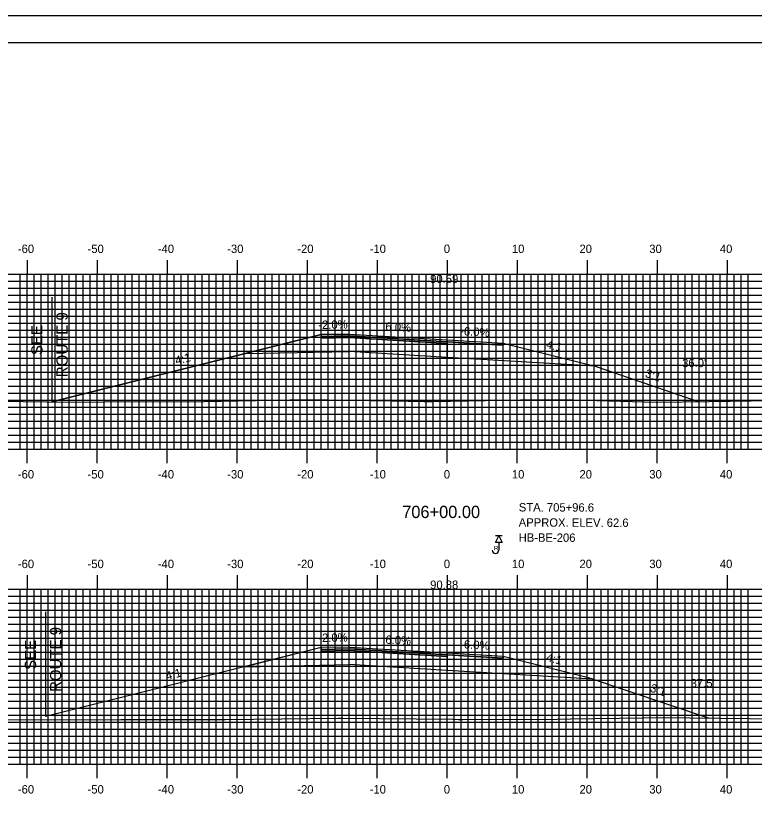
# Model space of a CAD drawing. Extents: x 853723 to 854066, y 364366 to 364586.
# Drawn here: x 853827.1 to 853932.6, y 364472.6 to 364585.7 of the extents above; entities that cross this region are included whole.
import ezdxf

# ---------------------------------------------------------------- set-up
doc = ezdxf.new("R2010")
doc.units = 0
for name, color, linetype in [('ANNOTATION', 7, 'Continuous'), ('BORDER', 7, 'Continuous'), ('BORING - REFUSAL', 7, 'Continuous'), ('D_Roadway_Centerline', 7, 'Continuous'), ('D_Roadway_Centerline_Text', 7, 'Continuous'), ('D_Roadway_Edge_Shoulder', 7, 'Continuous'), ('D_Roadway_Edge_TW', 7, 'Continuous'), ('D_Roadway_Pavement', 7, 'Continuous'), ('D_Roadway_SlopeLines', 7, 'Continuous'), ('D_Roadway_SubGrade', 7, 'Continuous'), ('D_Text_Standard', 7, 'Continuous'), ('H_V ANNOTATION', 7, 'Continuous'), ('MAJOR', 7, 'Continuous'), ('MINOR', 7, 'Continuous'), ('PLOT BOUNDARY', 7, 'Continuous'), ('S_Roadway_Centerline', 7, 'Continuous')]:
    doc.layers.add(name, color=color, linetype=linetype)

msp = doc.modelspace()

# ---------------------------------------------------------------- linework, layer by layer
at = {"layer": 'BORDER'}
msp.add_lwpolyline([(853739.12, 364371.79), (854059.12, 364371.79), (854059.12, 364581.79), (853739.12, 364581.79)], close=True, dxfattribs=at)
at = {"layer": 'BORING - REFUSAL'}
for p, q in [((853896.6, 364511.39), (853895.64, 364511.39)), ((853896.12, 364510.43), (853896.12, 364509.37))]:
    msp.add_line(p, q, dxfattribs=at)
msp.add_lwpolyline([(853896.12, 364511.39), (853896.6, 364510.43), (853895.64, 364510.43)], close=True, dxfattribs=at)
msp.add_arc((853895.63, 364509.37), 0.485, 180, 0, dxfattribs=at)
at = {"layer": 'D_Roadway_Centerline'}
msp.add_lwpolyline([(853832.23, 364530.52), (853859.85, 364537.42), (853870.72, 364540.14), (853874.72, 364540.22), (853888.72, 364539.38), (853896.72, 364538.9), (853908.72, 364535.9), (853909.88, 364535.61), (853924.73, 364530.56)], dxfattribs=at)
at = {"layer": 'D_Roadway_Edge_Shoulder'}
for points in [[(853874.72, 364540.22), (853870.72, 364540.14), (853870.72, 364539.89), (853874.72, 364539.97)], [(853888.72, 364539.38), (853896.72, 364538.9), (853896.72, 364538.65), (853888.72, 364539.13)], [(853874.72, 364495.51), (853870.72, 364495.43), (853870.72, 364495.18), (853874.72, 364495.26)], [(853888.72, 364494.67), (853896.72, 364494.19), (853896.72, 364493.94), (853888.72, 364494.42)]]:
    msp.add_lwpolyline(points, close=True, dxfattribs=at)
at = {"layer": 'D_Roadway_Edge_TW'}
for points in [[(853874.72, 364540.22), (853888.72, 364539.38), (853888.72, 364539.13), (853874.72, 364539.97)], [(853874.72, 364495.51), (853888.72, 364494.67), (853888.72, 364494.42), (853874.72, 364495.26)]]:
    msp.add_lwpolyline(points, close=True, dxfattribs=at)
at = {"layer": 'D_Roadway_Pavement'}
for points in [[(853874.72, 364539.97), (853870.72, 364539.89), (853870.72, 364539.64), (853874.72, 364539.72)], [(853874.72, 364539.97), (853888.72, 364539.13), (853888.72, 364538.88), (853874.72, 364539.72)], [(853874.72, 364495.26), (853870.72, 364495.18), (853870.72, 364494.93), (853874.72, 364495.01)], [(853874.72, 364495.26), (853888.72, 364494.42), (853888.72, 364494.17), (853874.72, 364495.01)]]:
    msp.add_lwpolyline(points, close=True, dxfattribs=at)
for points in [[(853888.72, 364539.13), (853888.72, 364538.88)], [(853888.72, 364539.13), (853888.72, 364538.88)], [(853888.72, 364494.42), (853888.72, 364494.17)], [(853888.72, 364494.42), (853888.72, 364494.17)]]:
    msp.add_lwpolyline(points, dxfattribs=at)
at = {"layer": 'D_Roadway_SlopeLines'}
for points in [[(853870.72, 364540.14), (853832.23, 364530.52)], [(853896.72, 364538.9), (853908.72, 364535.9), (853909.88, 364535.61), (853924.73, 364530.56)], [(853870.72, 364495.43), (853831.31, 364485.58)], [(853896.72, 364494.19), (853908.72, 364491.19), (853926.17, 364485.37)]]:
    msp.add_lwpolyline(points, dxfattribs=at)
at = {"layer": 'D_Roadway_SubGrade'}
for p, q in [((853832.23, 364545.48), (853832.23, 364530.52)), ((853831.31, 364500.53), (853831.31, 364485.58))]:
    msp.add_line(p, q, dxfattribs=at)
for points in [[(853874.72, 364539.72), (853870.72, 364539.64), (853870.72, 364539.89), (853870.72, 364540.14), (853859.85, 364537.42), (853874.72, 364537.72)], [(853874.72, 364539.72), (853888.72, 364538.88), (853888.72, 364536.88), (853874.72, 364537.72)], [(853888.72, 364538.88), (853888.72, 364539.13), (853896.72, 364538.65), (853896.72, 364538.9), (853909.88, 364535.61), (853888.72, 364536.88)], [(853874.72, 364495.01), (853870.72, 364494.93), (853870.72, 364495.18), (853870.72, 364495.43), (853859.85, 364492.71), (853874.72, 364493.01)], [(853874.72, 364495.01), (853888.72, 364494.17), (853888.72, 364492.17), (853874.72, 364493.01)], [(853888.72, 364494.17), (853888.72, 364494.42), (853896.72, 364493.94), (853896.72, 364494.19), (853908.72, 364491.19), (853909.52, 364490.92), (853888.72, 364492.17)]]:
    msp.add_lwpolyline(points, close=True, dxfattribs=at)
at = {"layer": 'MAJOR'}
for p, q in [((853828.72, 364550.79), (853828.72, 364548.79)), ((853838.72, 364550.79), (853838.72, 364548.79)), ((853848.72, 364550.79), (853848.72, 364548.79)), ((853858.72, 364550.79), (853858.72, 364548.79)), ((853868.72, 364550.79), (853868.72, 364548.79)), ((853878.72, 364550.79), (853878.72, 364548.79)), ((853888.72, 364550.79), (853888.72, 364548.79)), ((853898.72, 364550.79), (853898.72, 364548.79)), ((853908.72, 364550.79), (853908.72, 364548.79)), ((853918.72, 364550.79), (853918.72, 364548.79)), ((853928.72, 364550.79), (853928.72, 364548.79)), ((853748.72, 364548.79), (854028.72, 364548.79)), ((853748.72, 364548.79), (854028.72, 364548.79)), ((853828.72, 364523.79), (853828.72, 364548.79)), ((853838.72, 364523.79), (853838.72, 364548.79)), ((853848.72, 364523.79), (853848.72, 364548.79)), ((853858.72, 364523.79), (853858.72, 364548.79)), ((853868.72, 364523.79), (853868.72, 364548.79)), ((853878.72, 364523.79), (853878.72, 364548.79)), ((853888.72, 364523.79), (853888.72, 364548.79)), ((853898.72, 364523.79), (853898.72, 364548.79)), ((853908.72, 364523.79), (853908.72, 364548.79)), ((853918.72, 364523.79), (853918.72, 364548.79)), ((853928.72, 364523.79), (853928.72, 364548.79)), ((853748.72, 364543.79), (854028.72, 364543.79)), ((853748.72, 364538.79), (854028.72, 364538.79)), ((853748.72, 364533.79), (854028.72, 364533.79)), ((853748.72, 364528.79), (854028.72, 364528.79)), ((853748.72, 364523.79), (854028.72, 364523.79)), ((853748.72, 364523.79), (854028.72, 364523.79)), ((853828.72, 364521.78), (853828.72, 364523.79)), ((853838.72, 364521.78), (853838.72, 364523.79)), ((853848.72, 364521.78), (853848.72, 364523.79)), ((853858.72, 364521.78), (853858.72, 364523.79)), ((853868.72, 364521.78), (853868.72, 364523.79)), ((853878.72, 364521.78), (853878.72, 364523.79)), ((853888.72, 364521.78), (853888.72, 364523.79)), ((853898.72, 364521.78), (853898.72, 364523.79)), ((853908.72, 364521.78), (853908.72, 364523.79)), ((853918.72, 364521.78), (853918.72, 364523.79)), ((853928.72, 364521.78), (853928.72, 364523.79)), ((853828.72, 364505.79), (853828.72, 364503.79)), ((853838.72, 364505.79), (853838.72, 364503.79)), ((853848.72, 364505.79), (853848.72, 364503.79)), ((853858.72, 364505.79), (853858.72, 364503.79)), ((853868.72, 364505.79), (853868.72, 364503.79)), ((853878.72, 364505.79), (853878.72, 364503.79)), ((853888.72, 364505.79), (853888.72, 364503.79)), ((853898.72, 364505.79), (853898.72, 364503.79)), ((853908.72, 364505.79), (853908.72, 364503.79)), ((853918.72, 364505.79), (853918.72, 364503.79)), ((853928.72, 364505.79), (853928.72, 364503.79)), ((853748.72, 364503.79), (854028.72, 364503.79)), ((853748.72, 364503.79), (854028.72, 364503.79)), ((853828.72, 364478.79), (853828.72, 364503.79)), ((853838.72, 364478.79), (853838.72, 364503.79)), ((853848.72, 364478.79), (853848.72, 364503.79)), ((853858.72, 364478.79), (853858.72, 364503.79)), ((853868.72, 364478.79), (853868.72, 364503.79)), ((853878.72, 364478.79), (853878.72, 364503.79)), ((853888.72, 364478.79), (853888.72, 364503.79)), ((853898.72, 364478.79), (853898.72, 364503.79)), ((853908.72, 364478.79), (853908.72, 364503.79)), ((853918.72, 364478.79), (853918.72, 364503.79)), ((853928.72, 364478.79), (853928.72, 364503.79)), ((853748.72, 364498.79), (854028.72, 364498.79)), ((853748.72, 364493.79), (854028.72, 364493.79)), ((853748.72, 364488.79), (854028.72, 364488.79)), ((853748.72, 364483.79), (854028.72, 364483.79)), ((853748.72, 364478.79), (854028.72, 364478.79)), ((853748.72, 364478.79), (854028.72, 364478.79)), ((853828.72, 364476.78), (853828.72, 364478.79)), ((853838.72, 364476.78), (853838.72, 364478.79)), ((853848.72, 364476.78), (853848.72, 364478.79)), ((853858.72, 364476.78), (853858.72, 364478.79)), ((853868.72, 364476.78), (853868.72, 364478.79)), ((853878.72, 364476.78), (853878.72, 364478.79)), ((853888.72, 364476.78), (853888.72, 364478.79)), ((853898.72, 364476.78), (853898.72, 364478.79)), ((853908.72, 364476.78), (853908.72, 364478.79)), ((853918.72, 364476.78), (853918.72, 364478.79)), ((853928.72, 364476.78), (853928.72, 364478.79))]:
    msp.add_line(p, q, dxfattribs=at)
at = {"layer": 'MINOR'}
for p, q in [((853827.72, 364523.79), (853827.72, 364548.79)), ((853829.72, 364523.79), (853829.72, 364548.79)), ((853830.72, 364523.79), (853830.72, 364548.79)), ((853831.72, 364523.79), (853831.72, 364548.79)), ((853832.72, 364523.79), (853832.72, 364548.79)), ((853833.72, 364523.79), (853833.72, 364548.79)), ((853834.72, 364523.79), (853834.72, 364548.79)), ((853835.72, 364523.79), (853835.72, 364548.79)), ((853836.72, 364523.79), (853836.72, 364548.79)), ((853837.72, 364523.79), (853837.72, 364548.79)), ((853839.72, 364523.79), (853839.72, 364548.79)), ((853840.72, 364523.79), (853840.72, 364548.79)), ((853841.72, 364523.79), (853841.72, 364548.79)), ((853842.72, 364523.79), (853842.72, 364548.79)), ((853843.72, 364523.79), (853843.72, 364548.79)), ((853844.72, 364523.79), (853844.72, 364548.79)), ((853845.72, 364523.79), (853845.72, 364548.79)), ((853846.72, 364523.79), (853846.72, 364548.79)), ((853847.72, 364523.79), (853847.72, 364548.79)), ((853849.72, 364523.79), (853849.72, 364548.79)), ((853850.72, 364523.79), (853850.72, 364548.79)), ((853851.72, 364523.79), (853851.72, 364548.79)), ((853852.72, 364523.79), (853852.72, 364548.79)), ((853853.72, 364523.79), (853853.72, 364548.79)), ((853854.72, 364523.79), (853854.72, 364548.79)), ((853855.72, 364523.79), (853855.72, 364548.79)), ((853856.72, 364523.79), (853856.72, 364548.79)), ((853857.72, 364523.79), (853857.72, 364548.79)), ((853859.72, 364523.79), (853859.72, 364548.79)), ((853860.72, 364523.79), (853860.72, 364548.79)), ((853861.72, 364523.79), (853861.72, 364548.79)), ((853862.72, 364523.79), (853862.72, 364548.79)), ((853863.72, 364523.79), (853863.72, 364548.79)), ((853864.72, 364523.79), (853864.72, 364548.79)), ((853865.72, 364523.79), (853865.72, 364548.79)), ((853866.72, 364523.79), (853866.72, 364548.79)), ((853867.72, 364523.79), (853867.72, 364548.79)), ((853869.72, 364523.79), (853869.72, 364548.79)), ((853870.72, 364523.79), (853870.72, 364548.79)), ((853871.72, 364523.79), (853871.72, 364548.79)), ((853872.72, 364523.79), (853872.72, 364548.79)), ((853873.72, 364523.79), (853873.72, 364548.79)), ((853874.72, 364523.79), (853874.72, 364548.79)), ((853875.72, 364523.79), (853875.72, 364548.79)), ((853876.72, 364523.79), (853876.72, 364548.79)), ((853877.72, 364523.79), (853877.72, 364548.79)), ((853879.72, 364523.79), (853879.72, 364548.79)), ((853880.72, 364523.79), (853880.72, 364548.79)), ((853881.72, 364523.79), (853881.72, 364548.79)), ((853882.72, 364523.79), (853882.72, 364548.79)), ((853883.72, 364523.79), (853883.72, 364548.79)), ((853884.72, 364523.79), (853884.72, 364548.79)), ((853885.72, 364523.79), (853885.72, 364548.79)), ((853886.72, 364523.79), (853886.72, 364548.79)), ((853887.72, 364523.79), (853887.72, 364548.79)), ((853889.72, 364523.79), (853889.72, 364548.79)), ((853890.72, 364523.79), (853890.72, 364548.79)), ((853891.72, 364523.79), (853891.72, 364548.79)), ((853892.72, 364523.79), (853892.72, 364548.79)), ((853893.72, 364523.79), (853893.72, 364548.79)), ((853894.72, 364523.79), (853894.72, 364548.79)), ((853895.72, 364523.79), (853895.72, 364548.79)), ((853896.72, 364523.79), (853896.72, 364548.79)), ((853897.72, 364523.79), (853897.72, 364548.79)), ((853899.72, 364523.79), (853899.72, 364548.79)), ((853900.72, 364523.79), (853900.72, 364548.79)), ((853901.72, 364523.79), (853901.72, 364548.79)), ((853902.72, 364523.79), (853902.72, 364548.79)), ((853903.72, 364523.79), (853903.72, 364548.79)), ((853904.72, 364523.79), (853904.72, 364548.79)), ((853905.72, 364523.79), (853905.72, 364548.79)), ((853906.72, 364523.79), (853906.72, 364548.79)), ((853907.72, 364523.79), (853907.72, 364548.79)), ((853909.72, 364523.79), (853909.72, 364548.79)), ((853910.72, 364523.79), (853910.72, 364548.79)), ((853911.72, 364523.79), (853911.72, 364548.79)), ((853912.72, 364523.79), (853912.72, 364548.79)), ((853913.72, 364523.79), (853913.72, 364548.79)), ((853914.72, 364523.79), (853914.72, 364548.79)), ((853915.72, 364523.79), (853915.72, 364548.79)), ((853916.72, 364523.79), (853916.72, 364548.79)), ((853917.72, 364523.79), (853917.72, 364548.79)), ((853919.72, 364523.79), (853919.72, 364548.79)), ((853920.72, 364523.79), (853920.72, 364548.79)), ((853921.72, 364523.79), (853921.72, 364548.79)), ((853922.72, 364523.79), (853922.72, 364548.79)), ((853923.72, 364523.79), (853923.72, 364548.79)), ((853924.72, 364523.79), (853924.72, 364548.79)), ((853925.72, 364523.79), (853925.72, 364548.79)), ((853926.72, 364523.79), (853926.72, 364548.79)), ((853927.72, 364523.79), (853927.72, 364548.79)), ((853929.72, 364523.79), (853929.72, 364548.79)), ((853930.72, 364523.79), (853930.72, 364548.79)), ((853931.72, 364523.79), (853931.72, 364548.79)), ((853748.72, 364547.79), (854028.72, 364547.79)), ((853748.72, 364546.79), (854028.72, 364546.79)), ((853748.72, 364545.79), (854028.72, 364545.79)), ((853748.72, 364544.79), (854028.72, 364544.79)), ((853748.72, 364542.79), (854028.72, 364542.79)), ((853748.72, 364541.79), (854028.72, 364541.79)), ((853748.72, 364540.79), (854028.72, 364540.79)), ((853748.72, 364539.79), (854028.72, 364539.79)), ((853748.72, 364537.79), (854028.72, 364537.79)), ((853748.72, 364536.79), (854028.72, 364536.79)), ((853748.72, 364535.79), (854028.72, 364535.79)), ((853748.72, 364534.79), (854028.72, 364534.79)), ((853748.72, 364532.79), (854028.72, 364532.79)), ((853748.72, 364531.79), (854028.72, 364531.79)), ((853748.72, 364530.79), (854028.72, 364530.79)), ((853748.72, 364529.79), (854028.72, 364529.79)), ((853748.72, 364527.79), (854028.72, 364527.79)), ((853748.72, 364526.79), (854028.72, 364526.79)), ((853748.72, 364525.79), (854028.72, 364525.79)), ((853748.72, 364524.79), (854028.72, 364524.79)), ((853827.72, 364478.79), (853827.72, 364503.79)), ((853829.72, 364478.79), (853829.72, 364503.79)), ((853830.72, 364478.79), (853830.72, 364503.79)), ((853831.72, 364478.79), (853831.72, 364503.79)), ((853832.72, 364478.79), (853832.72, 364503.79)), ((853833.72, 364478.79), (853833.72, 364503.79)), ((853834.72, 364478.79), (853834.72, 364503.79)), ((853835.72, 364478.79), (853835.72, 364503.79)), ((853836.72, 364478.79), (853836.72, 364503.79)), ((853837.72, 364478.79), (853837.72, 364503.79)), ((853839.72, 364478.79), (853839.72, 364503.79)), ((853840.72, 364478.79), (853840.72, 364503.79)), ((853841.72, 364478.79), (853841.72, 364503.79)), ((853842.72, 364478.79), (853842.72, 364503.79)), ((853843.72, 364478.79), (853843.72, 364503.79)), ((853844.72, 364478.79), (853844.72, 364503.79)), ((853845.72, 364478.79), (853845.72, 364503.79)), ((853846.72, 364478.79), (853846.72, 364503.79)), ((853847.72, 364478.79), (853847.72, 364503.79)), ((853849.72, 364478.79), (853849.72, 364503.79)), ((853850.72, 364478.79), (853850.72, 364503.79)), ((853851.72, 364478.79), (853851.72, 364503.79)), ((853852.72, 364478.79), (853852.72, 364503.79)), ((853853.72, 364478.79), (853853.72, 364503.79)), ((853854.72, 364478.79), (853854.72, 364503.79)), ((853855.72, 364478.79), (853855.72, 364503.79)), ((853856.72, 364478.79), (853856.72, 364503.79)), ((853857.72, 364478.79), (853857.72, 364503.79)), ((853859.72, 364478.79), (853859.72, 364503.79)), ((853860.72, 364478.79), (853860.72, 364503.79)), ((853861.72, 364478.79), (853861.72, 364503.79)), ((853862.72, 364478.79), (853862.72, 364503.79)), ((853863.72, 364478.79), (853863.72, 364503.79)), ((853864.72, 364478.79), (853864.72, 364503.79)), ((853865.72, 364478.79), (853865.72, 364503.79)), ((853866.72, 364478.79), (853866.72, 364503.79)), ((853867.72, 364478.79), (853867.72, 364503.79)), ((853869.72, 364478.79), (853869.72, 364503.79)), ((853870.72, 364478.79), (853870.72, 364503.79)), ((853871.72, 364478.79), (853871.72, 364503.79)), ((853872.72, 364478.79), (853872.72, 364503.79)), ((853873.72, 364478.79), (853873.72, 364503.79)), ((853874.72, 364478.79), (853874.72, 364503.79)), ((853875.72, 364478.79), (853875.72, 364503.79)), ((853876.72, 364478.79), (853876.72, 364503.79)), ((853877.72, 364478.79), (853877.72, 364503.79)), ((853879.72, 364478.79), (853879.72, 364503.79)), ((853880.72, 364478.79), (853880.72, 364503.79)), ((853881.72, 364478.79), (853881.72, 364503.79)), ((853882.72, 364478.79), (853882.72, 364503.79)), ((853883.72, 364478.79), (853883.72, 364503.79)), ((853884.72, 364478.79), (853884.72, 364503.79)), ((853885.72, 364478.79), (853885.72, 364503.79)), ((853886.72, 364478.79), (853886.72, 364503.79)), ((853887.72, 364478.79), (853887.72, 364503.79)), ((853889.72, 364478.79), (853889.72, 364503.79)), ((853890.72, 364478.79), (853890.72, 364503.79)), ((853891.72, 364478.79), (853891.72, 364503.79)), ((853892.72, 364478.79), (853892.72, 364503.79)), ((853893.72, 364478.79), (853893.72, 364503.79)), ((853894.72, 364478.79), (853894.72, 364503.79)), ((853895.72, 364478.79), (853895.72, 364503.79)), ((853896.72, 364478.79), (853896.72, 364503.79)), ((853897.72, 364478.79), (853897.72, 364503.79)), ((853899.72, 364478.79), (853899.72, 364503.79)), ((853900.72, 364478.79), (853900.72, 364503.79)), ((853901.72, 364478.79), (853901.72, 364503.79)), ((853902.72, 364478.79), (853902.72, 364503.79)), ((853903.72, 364478.79), (853903.72, 364503.79)), ((853904.72, 364478.79), (853904.72, 364503.79)), ((853905.72, 364478.79), (853905.72, 364503.79)), ((853906.72, 364478.79), (853906.72, 364503.79)), ((853907.72, 364478.79), (853907.72, 364503.79)), ((853909.72, 364478.79), (853909.72, 364503.79)), ((853910.72, 364478.79), (853910.72, 364503.79)), ((853911.72, 364478.79), (853911.72, 364503.79)), ((853912.72, 364478.79), (853912.72, 364503.79)), ((853913.72, 364478.79), (853913.72, 364503.79)), ((853914.72, 364478.79), (853914.72, 364503.79)), ((853915.72, 364478.79), (853915.72, 364503.79)), ((853916.72, 364478.79), (853916.72, 364503.79)), ((853917.72, 364478.79), (853917.72, 364503.79)), ((853919.72, 364478.79), (853919.72, 364503.79)), ((853920.72, 364478.79), (853920.72, 364503.79)), ((853921.72, 364478.79), (853921.72, 364503.79)), ((853922.72, 364478.79), (853922.72, 364503.79)), ((853923.72, 364478.79), (853923.72, 364503.79)), ((853924.72, 364478.79), (853924.72, 364503.79)), ((853925.72, 364478.79), (853925.72, 364503.79)), ((853926.72, 364478.79), (853926.72, 364503.79)), ((853927.72, 364478.79), (853927.72, 364503.79)), ((853929.72, 364478.79), (853929.72, 364503.79)), ((853930.72, 364478.79), (853930.72, 364503.79)), ((853931.72, 364478.79), (853931.72, 364503.79)), ((853748.72, 364502.79), (854028.72, 364502.79)), ((853748.72, 364501.79), (854028.72, 364501.79)), ((853748.72, 364500.79), (854028.72, 364500.79)), ((853748.72, 364499.79), (854028.72, 364499.79)), ((853748.72, 364497.79), (854028.72, 364497.79)), ((853748.72, 364496.79), (854028.72, 364496.79)), ((853748.72, 364495.79), (854028.72, 364495.79)), ((853748.72, 364494.79), (854028.72, 364494.79)), ((853748.72, 364492.79), (854028.72, 364492.79)), ((853748.72, 364491.79), (854028.72, 364491.79)), ((853748.72, 364490.79), (854028.72, 364490.79)), ((853748.72, 364489.79), (854028.72, 364489.79)), ((853748.72, 364487.79), (854028.72, 364487.79)), ((853748.72, 364486.79), (854028.72, 364486.79)), ((853748.72, 364485.79), (854028.72, 364485.79)), ((853748.72, 364484.79), (854028.72, 364484.79)), ((853748.72, 364482.79), (854028.72, 364482.79)), ((853748.72, 364481.79), (854028.72, 364481.79)), ((853748.72, 364480.79), (854028.72, 364480.79)), ((853748.72, 364479.79), (854028.72, 364479.79))]:
    msp.add_line(p, q, dxfattribs=at)
at = {"layer": 'PLOT BOUNDARY'}
msp.add_lwpolyline([(853722.93, 364365.67), (854062.93, 364365.67), (854062.93, 364585.67), (853722.93, 364585.67)], close=True, dxfattribs=at)
at = {"layer": 'S_Roadway_Centerline'}
for points in [[(853748.72, 364530.94), (853750.82, 364530.95), (853757.02, 364530.96), (853767.92, 364531.13), (853771.61, 364531.07), (853785, 364530.42), (853790.47, 364530.48), (853801.08, 364530.66), (853803.74, 364530.64), (853818.32, 364530.72), (853824.84, 364530.62), (853834.76, 364530.49), (853844.74, 364530.59), (853851.56, 364530.54), (853856.41, 364530.64), (853868.67, 364530.88), (853880.78, 364530.66), (853885.5, 364530.58), (853886.66, 364530.58), (853901.73, 364530.89), (853906.72, 364530.81), (853918.61, 364530.5), (853926.17, 364530.58), (853935.19, 364530.75)], [(853825.86, 364485.13), (853842.1, 364485.15), (853842.29, 364485.15), (853846.29, 364485.16), (853857.03, 364485.19), (853873.14, 364485.37), (853873.79, 364485.37), (853889.52, 364485.2), (853890.36, 364485.18), (853890.94, 364485.19), (853904.43, 364485.21), (853906.41, 364485.24), (853920.22, 364485.46), (853923.41, 364485.4), (853936.21, 364485.25)]]:
    msp.add_lwpolyline(points, dxfattribs=at)

# ---------------------------------------------------------------- texts
at = {"layer": 'ANNOTATION'}
for s, height, rotation, p in [('ROUTE 9', 1.6, 90, (853834.49, 364534.06)), ('-2.0%', 1.2, 1.1458, (853870.32, 364540.93)), ('6.0%', 1.2, 356.5664, (853879.87, 364540.72)), ('SEE', 1.6, 90, (853830.89, 364537.21)), ('-6.0%', 1.2, 356.5664, (853890.55, 364540.08)), ('4:1', 1.2, 345.9638, (853902.8, 364538.24)), ('4:1', 1.2, 14.0362, (853850.01, 364535.83)), ('3:1', 1.2, 341.231, (853916.92, 364534.13)), ('ROUTE 9', 1.6, 90, (853833.57, 364489.11)), ('-2.0%', 1.2, 1.1458, (853870.32, 364496.22)), ('SEE', 1.6, 90, (853829.97, 364492.26)), ('6.0%', 1.2, 356.5664, (853879.87, 364496)), ('-6.0%', 1.2, 356.5664, (853890.55, 364495.36)), ('4:1', 1.2, 345.9638, (853902.8, 364493.53)), ('4:1', 1.2, 14.0362, (853848.67, 364490.78)), ('3:1', 1.2, 341.2604, (853917.64, 364489.18))]:
    msp.add_text(s, height=height, rotation=rotation, dxfattribs=at).set_placement(p)
at = {"layer": 'BORING - REFUSAL'}
for s, p in [('STA. 705+96.6', (853898.96, 364514.88)), ('APPROX. ELEV. 62.6', (853898.95, 364512.72)), ('HB-BE-206', (853898.94, 364510.56))]:
    msp.add_text(s, height=1.2, rotation=359.8142, dxfattribs=at).set_placement(p)
msp.add_text('R', height=0.64, dxfattribs=at).set_placement((853895.41, 364509.31))
at = {"layer": 'D_Roadway_Centerline_Text'}
for s, p in [('90.59', (853886.29, 364547.5)), ('90.88', (853886.29, 364503.81))]:
    msp.add_text(s, height=1.2, dxfattribs=at).set_placement(p)
at = {"layer": 'D_Text_Standard'}
for s, p in [("36.0'", (853922.3, 364535.49)), ("37.5'", (853923.52, 364489.76))]:
    msp.add_text(s, height=1.2, dxfattribs=at).set_placement(p)
at = {"layer": 'H_V ANNOTATION'}
for s, height, p in [('-60', 1.2, (853827.37, 364551.79)), ('-50', 1.2, (853837.33, 364551.79)), ('-40', 1.2, (853847.37, 364551.79)), ('-30', 1.2, (853857.29, 364551.79)), ('-20', 1.2, (853867.3, 364551.79)), ('-10', 1.2, (853877.65, 364551.79)), ('0', 1.2, (853888.24, 364551.79)), ('10', 1.2, (853897.97, 364551.79)), ('20', 1.2, (853907.63, 364551.79)), ('30', 1.2, (853917.61, 364551.79)), ('40', 1.2, (853927.69, 364551.79)), ('-60', 1.2, (853827.37, 364519.59)), ('-50', 1.2, (853837.33, 364519.59)), ('-40', 1.2, (853847.37, 364519.59)), ('-30', 1.2, (853857.29, 364519.59)), ('-20', 1.2, (853867.3, 364519.59)), ('-10', 1.2, (853877.65, 364519.59)), ('0', 1.2, (853888.24, 364519.59)), ('10', 1.2, (853897.97, 364519.59)), ('20', 1.2, (853907.63, 364519.59)), ('30', 1.2, (853917.61, 364519.59)), ('40', 1.2, (853927.69, 364519.59)), ('706+00.00', 1.75, (853882.3, 364513.94)), ('-60', 1.2, (853827.37, 364506.79)), ('-50', 1.2, (853837.33, 364506.79)), ('-40', 1.2, (853847.37, 364506.79)), ('-30', 1.2, (853857.29, 364506.79)), ('-20', 1.2, (853867.3, 364506.79)), ('-10', 1.2, (853877.65, 364506.79)), ('0', 1.2, (853888.24, 364506.79)), ('10', 1.2, (853897.97, 364506.79)), ('20', 1.2, (853907.63, 364506.79)), ('30', 1.2, (853917.61, 364506.79)), ('40', 1.2, (853927.69, 364506.79)), ('-60', 1.2, (853827.37, 364474.59)), ('-50', 1.2, (853837.33, 364474.59)), ('-40', 1.2, (853847.37, 364474.59)), ('-30', 1.2, (853857.29, 364474.59)), ('-20', 1.2, (853867.3, 364474.59)), ('-10', 1.2, (853877.65, 364474.59)), ('0', 1.2, (853888.24, 364474.59)), ('10', 1.2, (853897.97, 364474.59)), ('20', 1.2, (853907.63, 364474.59)), ('30', 1.2, (853917.61, 364474.59)), ('40', 1.2, (853927.69, 364474.59))]:
    msp.add_text(s, height=height, dxfattribs=at).set_placement(p)

doc.saveas('drawing.dxf')
